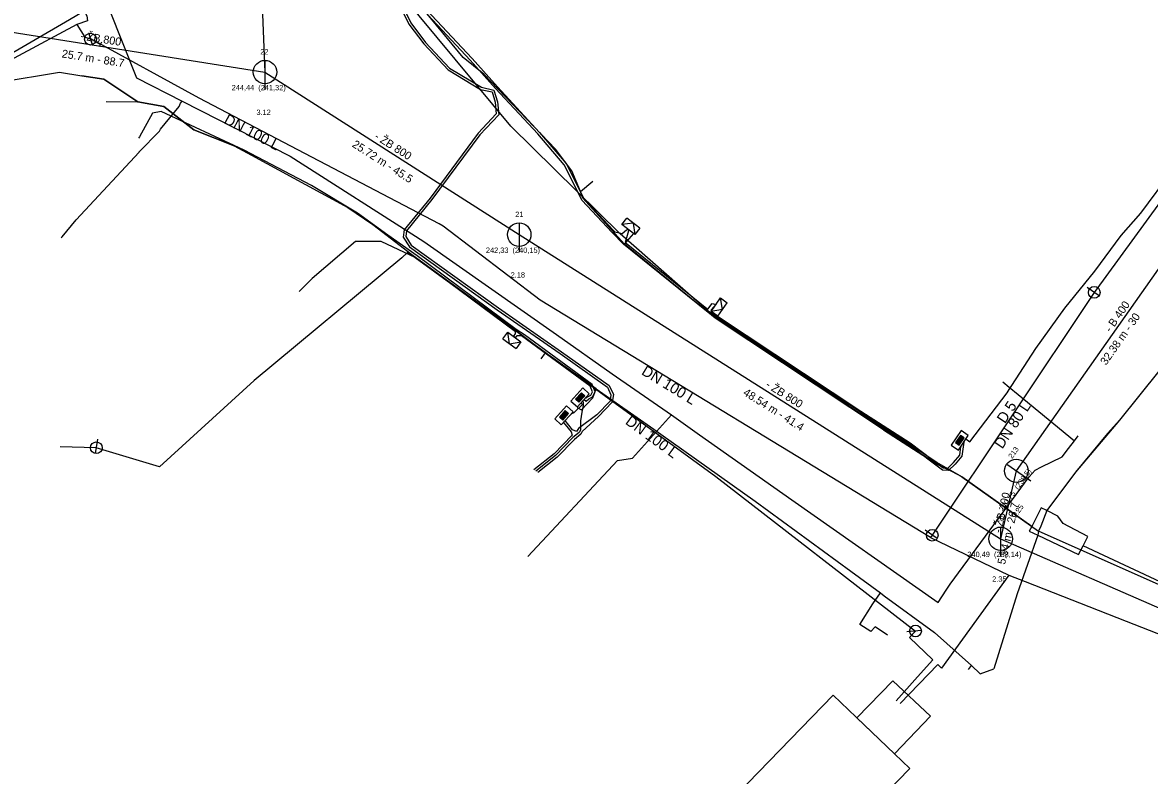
# Model space of a CAD drawing. Extents: x -600636 to -600148, y -1203980 to -1203569.
# Drawn here: x -600579.1 to -600483.1, y -1203856 to -1203791.8 of the extents above; entities that cross this region are included whole.
import ezdxf

# ---------------------------------------------------------------- set-up
doc = ezdxf.new("R2010")
doc.units = 0
for name, color, linetype in [('Cetin kolektor kabelovod', 7, 'Continuous'), ('Cetin nezaměřený', 7, 'Continuous'), ('Cetin NN přípojka', 7, 'Continuous'), ('Cetin zam průběh', 7, 'Continuous'), ('EON objekty', 7, 'Continuous'), ('EON podzemní NN', 7, 'Continuous'), ('GasNet NTL', 7, 'Continuous'), ('Implicitní', 7, 'Continuous'), ('VaK Břeclav_kanalizace', 7, 'Continuous'), ('VaK Břeclav_kanalizace_popis', 7, 'Continuous'), ('Vak Břeclav_vodovod', 7, 'Continuous'), ('Vak Břeclav_vodovod_popis', 7, 'Continuous'), ('Vrstva 9', 7, 'Continuous')]:
    doc.layers.add(name, color=color, linetype=linetype)

# ---------------------------------------------------------------- blocks, each defined once
blk = doc.blocks.new('NN630')
at = {"layer": 'Vrstva 9'}
for points in [[(-0.003, -0.7), (-0.703, 0)], [(-0.703, -0.7), (-0.703, 0), (0.697, 0), (0.697, -0.7)], [(-0.703, -0.7), (0.697, -0.7)], [(-0.003, -0.7), (0.697, 0)]]:
    blk.add_lwpolyline(points, dxfattribs=at)
blk = doc.blocks.new('NN620')
at = {"layer": 'EON objekty'}
for points in [[(0.752, 0.004), (-0.748, 0.004)], [(-0.748, 0.004), (-0.748, -0.746)], [(0.752, -0.746), (0.752, 0.004)], [(-0.748, -0.746), (0.752, -0.746)], [(0.368, -0.18), (-0.376, -0.18)], [(-0.376, -0.18), (-0.376, -0.558)], [(-0.376, -0.558), (0.368, -0.558)], [(0.321, -0.227), (-0.329, -0.227)], [(-0.329, -0.227), (-0.329, -0.51)], [(-0.329, -0.51), (0.321, -0.51)], [(0.274, -0.274), (-0.281, -0.274)], [(-0.281, -0.274), (-0.281, -0.463)], [(-0.281, -0.463), (0.274, -0.463)], [(0.227, -0.321), (-0.234, -0.321)], [(-0.234, -0.321), (-0.234, -0.416)], [(-0.234, -0.416), (0.227, -0.416)], [(-0.193, -0.369), (0.185, -0.369)], [(0.227, -0.416), (0.227, -0.321)], [(0.274, -0.463), (0.274, -0.274)], [(0.321, -0.51), (0.321, -0.227)], [(0.368, -0.558), (0.368, -0.18)]]:
    blk.add_lwpolyline(points, dxfattribs=at)
blk = doc.blocks.new('MoSymbol 2')
at = {"layer": 'Implicitní'}
blk.add_line((0, 0.0005), (0, -0.00075), dxfattribs=at)
blk.add_circle((0, 0), 0.0005, dxfattribs=at)
blk = doc.blocks.new('MoSymbol 3')
at = {"layer": 'Implicitní'}
for p, q in [((-0.000365, -0.000365), (0.000365, 0.000365)), ((-0.000225, 0.00095), (0.000225, 0.00095)), ((0, 0.00095), (0, 0.0005))]:
    blk.add_line(p, q, dxfattribs=at)
blk.add_circle((0, 0), 0.0005, dxfattribs=at)

msp = doc.modelspace()

# ---------------------------------------------------------------- linework, layer by layer
at = {"layer": 'Cetin kolektor kabelovod'}
for points in [[(-600458.68, -1203800.12), (-600462.14, -1203802.25), (-600474.23, -1203812.68), (-600476.82, -1203815.05), (-600480.09, -1203818.86), (-600482.26, -1203821.55), (-600485.61, -1203825.73), (-600486.63, -1203826.86), (-600489.37, -1203830.16), (-600491.81, -1203833.43)], [(-600493.1, -1203834.77), (-600499.06, -1203830.56)], [(-600492.59, -1203835.53), (-600494.35, -1203840.53), (-600496.33, -1203846.9)], [(-600469.44, -1203845.43), (-600488.73, -1203836.43)]]:
    msp.add_lwpolyline(points, dxfattribs=at)
msp.add_lwpolyline([(-600492.31, -1203833.18), (-600493.1, -1203834.77), (-600493.32, -1203835.19), (-600492.59, -1203835.53), (-600489.11, -1203837.17), (-600488.73, -1203836.43), (-600488.31, -1203835.63), (-600490.42, -1203834.52), (-600490.88, -1203833.89), (-600491.81, -1203833.43), (-600492.31, -1203833.18)], close=True, dxfattribs=at)
at = {"layer": 'Cetin nezaměřený'}
for points in [[(-600455.71, -1203797.64), (-600458.68, -1203800.12), (-600462.14, -1203802.25), (-600474.23, -1203812.68), (-600476.82, -1203815.05), (-600480.09, -1203818.86), (-600482.26, -1203821.55), (-600485.61, -1203825.73), (-600489.37, -1203830.16), (-600491.81, -1203833.43), (-600492.338, -1203834.75)], [(-600499.06, -1203830.56), (-600492.51, -1203835.18)], [(-600492.51, -1203835.18), (-600492.59, -1203835.53), (-600494.35, -1203840.53), (-600496.33, -1203846.9)], [(-600492.338, -1203834.75), (-600492.51, -1203835.18)], [(-600467.951, -1203845.887), (-600469.44, -1203845.43), (-600492.51, -1203835.18)]]:
    msp.add_lwpolyline(points, dxfattribs=at)
at = {"layer": 'Cetin NN přípojka'}
for points in [[(-600455.71, -1203797.64), (-600458.68, -1203800.12), (-600462.14, -1203802.25), (-600474.23, -1203812.68), (-600476.82, -1203815.05), (-600480.09, -1203818.86), (-600482.26, -1203821.55), (-600485.61, -1203825.73), (-600489.37, -1203830.16), (-600491.81, -1203833.43), (-600492.338, -1203834.75)], [(-600467.951, -1203845.887), (-600469.44, -1203845.43), (-600492.51, -1203835.18)]]:
    msp.add_lwpolyline(points, dxfattribs=at)
at = {"layer": 'Cetin zam průběh'}
for points in [[(-600499.06, -1203830.56), (-600501.19, -1203829.34), (-600520.52, -1203816.59), (-600528.18, -1203809.84), (-600537.51, -1203800.68), (-600551.58, -1203783.7), (-600551.71, -1203781.06), (-600528.73, -1203763.94), (-600503.65, -1203745.81), (-600492.34, -1203738.04), (-600490.82, -1203737.26)], [(-600531.56, -1203806.25), (-600532.29, -1203804.48), (-600533.68, -1203802.64), (-600539.8, -1203796.23), (-600541.55, -1203794.83), (-600547.3, -1203787.83)], [(-600591.27, -1203810.59), (-600590.6, -1203806.73), (-600588.32, -1203802.51), (-600586.01, -1203800.08), (-600583.97, -1203798.69), (-600581.13, -1203796.91), (-600575.98, -1203796.07), (-600574.075, -1203796.372)], [(-600559.619, -1203803.142), (-600561.08, -1203802.35), (-600564.511, -1203800.977), (-600567.065, -1203798.986), (-600569.3, -1203798.61), (-600572.19, -1203796.67), (-600574.075, -1203796.372)], [(-600574.075, -1203796.372), (-600572.19, -1203796.67), (-600569.3, -1203798.61)], [(-600572, -1203798.58), (-600569.3, -1203798.61)], [(-600569.3, -1203798.61), (-600567.065, -1203798.986), (-600564.511, -1203800.977), (-600561.08, -1203802.35), (-600559.619, -1203803.142)], [(-600559.619, -1203803.142), (-600551.4, -1203807.6), (-600549.27, -1203809.06), (-600545.93, -1203811.62), (-600537.49, -1203817.74), (-600534.55, -1203819.98)], [(-600531.56, -1203806.25), (-600530.51, -1203805.37)], [(-600527.81, -1203810.73), (-600531.35, -1203806.8), (-600531.56, -1203806.25)], [(-600527.81, -1203810.73), (-600527.03, -1203809.81)], [(-600499.91, -1203830.09), (-600501.11, -1203829.54), (-600505.73, -1203826.55), (-600520.08, -1203817.03), (-600527.81, -1203810.73)], [(-600534.91, -1203820.49), (-600534.55, -1203819.98)], [(-600530.24, -1203823.04), (-600534.55, -1203819.98)], [(-600531.85, -1203824.63), (-600531.47, -1203824.85), (-600530.5, -1203823.83), (-600530.24, -1203823.04)], [(-600530.24, -1203823.04), (-600525.32, -1203826.5)], [(-600530.24, -1203823.04), (-600525.32, -1203826.5), (-600524.71, -1203826.92), (-600516.67, -1203832.62), (-600508.52, -1203838.59), (-600506, -1203840.44)], [(-600505.73, -1203826.55), (-600501.11, -1203829.54)], [(-600499.06, -1203830.56), (-600499.91, -1203830.09)], [(-600505.4, -1203844.05), (-600506.46, -1203843.33), (-600506.81, -1203843.72), (-600507.74, -1203843.13), (-600506.64, -1203841.38), (-600506, -1203840.44)], [(-600506, -1203840.44), (-600505.68, -1203840.68)], [(-600505.68, -1203840.68), (-600501.38, -1203843.81), (-600498.24, -1203846.62)], [(-600498.5, -1203846.98), (-600498.24, -1203846.62)], [(-600498.24, -1203846.62), (-600497.5, -1203847.34), (-600496.33, -1203846.9)]]:
    msp.add_lwpolyline(points, dxfattribs=at)
at = {"layer": 'EON podzemní NN'}
for points in [[(-600498.901, -1203827.602), (-600499.048, -1203828.781), (-600499.614, -1203829.48), (-600500.19, -1203830.005), (-600500.719, -1203829.995), (-600503.581, -1203827.811), (-600507.769, -1203825.121), (-600520.828, -1203816.426), (-600527.906, -1203810.724), (-600528.879, -1203809.711), (-600531.41, -1203807.006), (-600532.963, -1203803.963), (-600535.195, -1203801.335), (-600538.795, -1203797.466), (-600540.961, -1203795.042), (-600546.971, -1203788.6)], [(-600546.825, -1203788.464), (-600540.809, -1203794.912), (-600538.645, -1203797.333), (-600535.047, -1203801.199), (-600532.795, -1203803.851), (-600531.244, -1203806.89), (-600528.775, -1203809.531), (-600528.631, -1203809.667), (-600528.008, -1203809.814), (-600527.648, -1203809.494), (-600527.494, -1203809.477), (-600527.475, -1203809.597), (-600527.766, -1203810.57), (-600527.682, -1203810.648), (-600520.787, -1203816.199), (-600520.71, -1203816.264), (-600520.34, -1203815.795), (-600520.029, -1203815.877), (-600520.438, -1203816.332), (-600520.455, -1203816.458), (-600519.875, -1203816.869), (-600507.659, -1203824.953), (-600503.467, -1203827.647), (-600500.649, -1203829.797), (-600500.266, -1203829.803), (-600499.76, -1203829.342), (-600499.24, -1203828.699), (-600499.147, -1203827.96)], [(-600546.802, -1203790.768), (-600546.203, -1203791.975), (-600544.92, -1203793.665), (-600542.85, -1203795.874), (-600540.073, -1203797.534), (-600539.095, -1203797.733), (-600538.842, -1203798.618), (-600538.743, -1203799.625), (-600540.288, -1203801.273), (-600544.389, -1203806.794), (-600546.59, -1203809.506), (-600546.67, -1203810.13), (-600546.142, -1203810.954), (-600538.655, -1203816.316), (-600533.302, -1203820.051), (-600529.269, -1203822.91), (-600528.965, -1203823.551), (-600529.045, -1203824.09), (-600530.173, -1203825.263), (-600531.728, -1203826.436), (-600531.898, -1203826.694), (-600532.243, -1203826.548), (-600532.879, -1203825.76)], [(-600546.634, -1203790.658), (-600546.033, -1203791.869), (-600544.766, -1203793.535), (-600542.724, -1203795.716), (-600540.011, -1203797.338), (-600538.945, -1203797.6), (-600538.644, -1203798.596), (-600538.535, -1203799.695), (-600540.134, -1203801.401), (-600544.231, -1203806.916), (-600546.398, -1203809.588), (-600546.462, -1203810.084), (-600545.994, -1203810.814), (-600538.539, -1203816.152), (-600533.186, -1203819.887), (-600529.111, -1203822.778), (-600528.759, -1203823.521), (-600528.857, -1203824.182), (-600530.037, -1203825.409), (-600531.414, -1203826.694), (-600531.533, -1203826.912), (-600532.076, -1203827.356), (-600533.551, -1203828.875), (-600535.198, -1203830.192)], [(-600531.253, -1203823.962), (-600531.084, -1203824.114), (-600530.84, -1203823.898), (-600530.529, -1203823.726), (-600530.31, -1203823.317), (-600530.571, -1203822.692), (-600536.337, -1203818.456), (-600537.034, -1203818.002), (-600545.488, -1203811.73), (-600547.972, -1203809.954), (-600550.581, -1203808.073), (-600554.496, -1203805.739), (-600560.229, -1203802.702), (-600567.308, -1203799.424), (-600568.053, -1203799.566), (-600569.14, -1203801.592), (-600569.228, -1203801.703)], [(-600498.707, -1203827.322), (-600498.371, -1203827.561), (-600495.205, -1203823.392), (-600495.012, -1203823.098), (-600494.793, -1203822.764), (-600492.738, -1203819.629), (-600490.281, -1203816.191), (-600487.73, -1203813.039), (-600485.469, -1203810), (-600483.801, -1203808.07), (-600481.102, -1203804.461)], [(-600531.118, -1203823.814), (-600531.083, -1203823.846), (-600530.956, -1203823.734), (-600530.677, -1203823.58), (-600530.532, -1203823.307), (-600530.735, -1203822.82), (-600536.581, -1203818.535), (-600536.984, -1203818.529), (-600537.069, -1203818.639), (-600537.199, -1203818.644), (-600537.233, -1203818.524), (-600537.102, -1203818.352), (-600537.096, -1203818.2), (-600545.588, -1203811.904), (-600548.567, -1203810.491), (-600550.739, -1203810.499), (-600554.434, -1203813.648), (-600555.544, -1203814.765)], [(-600531.387, -1203824.11), (-600531.327, -1203824.164), (-600531.341, -1203824.473), (-600531.443, -1203825.033), (-600531.569, -1203825.785), (-600531.571, -1203826.565), (-600531.69, -1203826.782), (-600532.211, -1203827.208), (-600533.686, -1203828.727), (-600535.362, -1203830.067)], [(-600532.356, -1203825.181), (-600532.116, -1203825.078), (-600531.388, -1203824.379), (-600531.521, -1203824.259)], [(-600533.015, -1203825.91), (-600532.36, -1203826.723), (-600532.274, -1203827.001), (-600532.299, -1203827.021), (-600533.821, -1203828.579), (-600535.527, -1203829.942)]]:
    msp.add_lwpolyline(points, dxfattribs=at)
at = {"layer": 'GasNet NTL'}
for points in [[(-600575.24, -1203781.91), (-600569.42, -1203796.55), (-600565.52, -1203798.53), (-600556.3, -1203803.23), (-600544.92, -1203810.5), (-600533.6, -1203818.43), (-600528.85, -1203821.76), (-600523.82, -1203825.28), (-600521.43, -1203826.96)], [(-600575.82, -1203810.18), (-600575.75, -1203810.11), (-600574.54, -1203808.64), (-600569.19, -1203802.88), (-600569.18, -1203802.87), (-600567.44, -1203801.1), (-600567.35, -1203800.94), (-600565.78, -1203799), (-600565.65, -1203798.71)], [(-600565.65, -1203798.71), (-600565.52, -1203798.53)], [(-600495.55, -1203822.47), (-600495.03, -1203822.9), (-600494.25, -1203823.53), (-600489.46, -1203827.48)], [(-600536.06, -1203837.33), (-600528.41, -1203829.16), (-600527.14, -1203828.95), (-600523.82, -1203825.28)], [(-600521.43, -1203826.96), (-600513.55, -1203832.51), (-600501.08, -1203841.26)], [(-600501.08, -1203841.26), (-600500.39, -1203840.2), (-600500.05, -1203839.69), (-600493.31, -1203830.56), (-600492.82, -1203829.97), (-600492.28, -1203829.71), (-600490.5, -1203828.86), (-600489.96, -1203828.14), (-600489.46, -1203827.48), (-600489.14, -1203827.05)]]:
    msp.add_lwpolyline(points, dxfattribs=at)
at = {"layer": 'VaK Břeclav_kanalizace'}
for p, q in [((-600559.203, -1203778.746), (-600558.458, -1203796.062)), ((-600583.84, -1203792.047), (-600558.458, -1203796.062)), ((-600558.458, -1203796.062), (-600536.788, -1203809.913)), ((-600475.798, -1203803.548), (-600494.416, -1203830.039)), ((-600536.788, -1203809.913), (-600495.75, -1203835.832)), ((-600494.416, -1203830.039), (-600495.75, -1203835.832)), ((-600495.75, -1203835.832), (-600460.179, -1203851.393))]:
    msp.add_line(p, q, dxfattribs=at)
at = {"layer": 'Vak Břeclav_vodovod'}
for p, q in [((-600573.583, -1203791.689), (-600574.494, -1203791.995)), ((-600487.771, -1203814.834), (-600501.58, -1203835.528)), ((-600572.834, -1203828.073), (-600575.925, -1203827.998)), ((-600501.58, -1203835.528), (-600501.725, -1203835.732)), ((-600501.725, -1203835.732), (-600495.042, -1203838.922))]:
    msp.add_line(p, q, dxfattribs=at)
for points in [[(-600395.742, -1203804.116), (-600404.972, -1203798.52), (-600440.983, -1203772.83), (-600445.608, -1203769.543), (-600461.034, -1203783.688), (-600477.697, -1203801.016), (-600487.771, -1203814.834)], [(-600612.162, -1203773.201), (-600602.995, -1203784.637), (-600601.189, -1203803.343), (-600600.899, -1203803.294), (-600597.986, -1203803.077), (-600584.599, -1203797.079), (-600575.117, -1203791.572), (-600573.857, -1203790.834), (-600573.636, -1203791.26), (-600573.583, -1203791.689)], [(-600574.494, -1203791.995), (-600584.471, -1203797.336), (-600598.082, -1203803.451), (-600600.849, -1203803.933)], [(-600574.494, -1203791.995), (-600573.818, -1203793.079), (-600573.314, -1203793.223)], [(-600543.62, -1203808.994), (-600564.069, -1203798.292), (-600573.314, -1203793.223)], [(-600501.725, -1203835.732), (-600535.01, -1203815.503), (-600543.268, -1203809.178), (-600543.62, -1203808.994)], [(-600546.269, -1203811.419), (-600546.778, -1203811.885), (-600559.369, -1203822.342)], [(-600546.269, -1203811.419), (-600520.034, -1203830.527), (-600503.008, -1203843.689)], [(-600559.369, -1203822.342), (-600567.456, -1203829.697), (-600572.834, -1203828.073)], [(-600495.042, -1203838.922), (-600500.786, -1203846.842), (-600501.115, -1203846.535), (-600504.315, -1203849.877)], [(-600495.042, -1203838.922), (-600493.648, -1203839.468), (-600485.045, -1203842.841)], [(-600485.045, -1203842.841), (-600467.036, -1203849.899), (-600453.613, -1203855.401), (-600438.627, -1203864.89), (-600435.585, -1203867.866)], [(-600504.656, -1203849.645), (-600502.831, -1203847.587), (-600501.541, -1203846.133), (-600503.527, -1203844.231), (-600503.008, -1203843.689)]]:
    msp.add_lwpolyline(points, dxfattribs=at)
for points in [[(-600504.945, -1203847.936), (-600501.726, -1203850.936), (-600504.788, -1203854.151), (-600507.997, -1203851.078)], [(-600510.02, -1203849.154), (-600503.496, -1203855.416), (-600512.788, -1203864.932), (-600519.116, -1203858.536)]]:
    msp.add_lwpolyline(points, close=True, dxfattribs=at)

# ---------------------------------------------------------------- block references
at = {"layer": 'EON podzemní NN'}
for name, p, rotation in [('NN630', (-600527.494, -1203809.477), 142.25484158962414), ('NN630', (-600520.029, -1203815.877), 54.74496668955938), ('NN630', (-600537.199, -1203818.644), -36.15030569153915), ('NN620', (-600531.321, -1203824.035), -132.12986106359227), ('NN620', (-600532.699, -1203825.559), -132.12986106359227), ('NN620', (-600498.934, -1203827.65), -124.45318894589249)]:
    msp.add_blockref(name, p, dxfattribs=dict(at, rotation=rotation))
at = {"layer": 'VaK Břeclav_kanalizace', "xscale": 1999.750031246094, "yscale": 1999.750031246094}
for p in [(-600558.458, -1203796.062), (-600536.788, -1203809.913), (-600495.75, -1203835.832)]:
    msp.add_blockref('MoSymbol 2', p, dxfattribs=at)
at = {"layer": 'VaK Břeclav_kanalizace', "xscale": 1999.7500312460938, "yscale": 1999.7500312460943, "rotation": 54.77919011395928}
msp.add_blockref('MoSymbol 2', (-600494.416, -1203830.039), dxfattribs=at)
at = {"layer": 'Vak Břeclav_vodovod'}
for name, p, xscale, yscale, rotation in [('MoSymbol 3', (-600573.331, -1203793.256), 999.8750156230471, 999.875015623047, -117.98322017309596), ('MoSymbol 2', (-600487.771, -1203814.834), 999.875015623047, 999.875015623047, -124.90443168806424), ('MoSymbol 2', (-600572.834, -1203828.073), 999.8750156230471, 999.8750156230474, 170.91124920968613), ('MoSymbol 2', (-600501.58, -1203835.528), 999.8750156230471, 999.8750156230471, -124.55979820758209), ('MoSymbol 2', (-600503.008, -1203843.689), 999.875015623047, 999.8750156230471, -85.73199708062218)]:
    msp.add_blockref(name, p, dxfattribs=dict(at, xscale=xscale, yscale=yscale, rotation=rotation))

# ---------------------------------------------------------------- texts
at = {"layer": 'VaK Břeclav_kanalizace_popis'}
for s, height, rotation, p in [('- ŽB 800', 0.6824, 351.011, (-600574.227, -1203793.285)), ('25.7 m - 88.7', 0.68241, 351.011, (-600575.81, -1203794.808)), ('25.72 m - 45.5', 0.68241, 327.41412, (-600551.086, -1203802.384)), ('- ŽB 800', 0.6824, 327.41412, (-600549.185, -1203801.707)), ('- B 400', 0.6824, 54.89923, (-600486.386, -1203818.283)), ('32.38 m - 30', 0.68241, 54.89923, (-600486.762, -1203821.087)), ('48.54 m - 41.4', 0.68241, 327.72378, (-600517.761, -1203823.538)), ('- ŽB 800', 0.6824, 327.72378, (-600515.844, -1203822.859)), ('213', 0.4549, 54.77919, (-600494.772, -1203829.043)), ('240,75  (238,5)', 0.45494, 54.77919, (-600495.557, -1203833.542)), ('- ŽB 400', 0.6824, 77.03258, (-600495.71, -1203835.374)), ('5.94 m - 26.7', 0.68241, 77.03258, (-600495.38, -1203838.066)), ('2.25', 0.4549, 54.77919, (-600494.463, -1203834.094))]:
    msp.add_text(s, height=height, rotation=rotation, dxfattribs=at).set_placement(p)
for s, height, p in [('22', 0.4549, (-600558.859, -1203794.562)), ('244,44  (241,32)', 0.45494, (-600561.296, -1203797.617)), ('3.12', 0.4549, (-600559.184, -1203799.717)), ('21', 0.4549, (-600537.124, -1203808.413)), ('242,33  (240,15)', 0.45494, (-600539.626, -1203811.468)), ('2.18', 0.4549, (-600537.514, -1203813.568)), ('20', 0.4549, (-600496.151, -1203834.332)), ('240,49  (238,14)', 0.45494, (-600498.588, -1203837.387)), ('2.35', 0.4549, (-600496.476, -1203839.487))]:
    msp.add_text(s, height=height, dxfattribs=at).set_placement(p)
at = {"layer": 'Vak Břeclav_vodovod_popis'}
for s, rotation, p in [('DN 100 L', 332.37513, (-600562.028, -1203800.387)), ('DN 100 L', 328.71081, (-600526.435, -1203821.779)), ('D 5', 56.28502, (-600495.385, -1203826.068)), ('DN 80 L', 56.28502, (-600495.614, -1203828.227)), ('DN 100 L', 323.93171, (-600527.809, -1203825.99))]:
    msp.add_text(s, height=0.9099, rotation=rotation, dxfattribs=at).set_placement(p)

doc.saveas('drawing.dxf')
